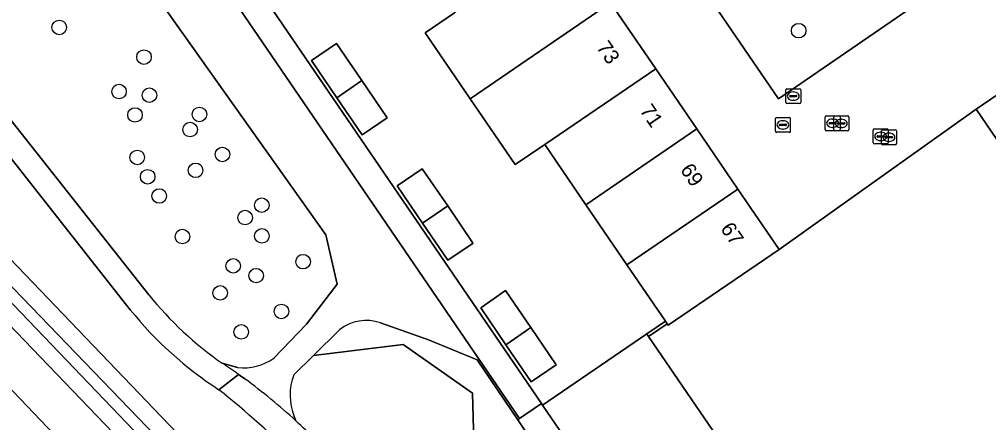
# Model space of a CAD drawing. Extents: x 155275 to 156265, y 382654 to 383635.
# Drawn here: x 155429.6 to 155494.7, y 382926 to 382953 of the extents above; entities that cross this region are included whole.
import ezdxf

# ---------------------------------------------------------------- set-up
doc = ezdxf.new("R2010")
doc.units = 0
for name, color, linetype in [('IMGEO_Boom', 7, 'Continuous'), ('IMGEO_Brandkraan', 7, 'Continuous'), ('IMGEO_Erf', 7, 'Continuous'), ('IMGEO_Fietspad_gesloten', 7, 'Continuous'), ('IMGEO_Groenvoorziening', 7, 'Continuous'), ('IMGEO_Muur', 7, 'Continuous'), ('IMGEO_Oever', 7, 'Continuous'), ('IMGEO_Pand', 7, 'Continuous'), ('IMGEO_Pand_nummerreeks', 7, 'Continuous'), ('IMGEO_Rioolput', 7, 'Continuous'), ('IMGEO_Voetpad_halfverhard', 7, 'Continuous'), ('IMGEO_Voetpad_open', 7, 'Continuous'), ('IMGEO_Waterloop', 7, 'Continuous')]:
    doc.layers.add(name, color=color, linetype=linetype)

msp = doc.modelspace()

# ---------------------------------------------------------------- linework, layer by layer
at = {"layer": 'IMGEO_Boom'}
for centre in [(155432.24, 382952.505), (155481.902, 382952.289), (155437.931, 382950.514), (155436.258, 382948.196), (155438.298, 382947.953), (155437.327, 382946.625), (155441.655, 382946.66), (155441.029, 382945.641), (155437.482, 382943.771), (155443.2, 382943.968), (155441.394, 382942.901), (155438.179, 382942.47), (155438.956, 382941.179), (155445.842, 382940.562), (155444.725, 382939.731), (155440.517, 382938.455), (155445.851, 382938.496), (155443.923, 382936.486), (155448.619, 382936.765), (155445.466, 382935.829), (155443.05, 382934.666), (155447.166, 382933.425), (155444.463, 382932.047)]:
    msp.add_circle(centre, 0.489, dxfattribs=at)
at = {"layer": 'IMGEO_Brandkraan'}
for p, q in [((155483.755, 382946.568), (155484.607, 382946.568)), ((155484.334, 382946.556), (155485.186, 382946.556)), ((155483.68, 382945.642), (155483.68, 382946.494)), ((155483.939, 382946.062), (155483.939, 382946.074)), ((155484.377, 382946.025), (155483.979, 382946.025)), ((155483.982, 382946.111), (155484.38, 382946.111)), ((155484.168, 382946.348), (155484.193, 382946.348)), ((155484.259, 382945.63), (155484.259, 382946.482)), ((155484.423, 382946.074), (155484.423, 382946.062)), ((155484.518, 382946.05), (155484.518, 382946.062)), ((155484.956, 382946.013), (155484.558, 382946.013)), ((155484.561, 382946.099), (155484.959, 382946.099)), ((155484.681, 382946.494), (155484.681, 382945.642)), ((155484.747, 382946.336), (155484.772, 382946.336)), ((155485.002, 382946.062), (155485.002, 382946.05)), ((155485.26, 382946.482), (155485.26, 382945.63)), ((155484.607, 382945.568), (155483.755, 382945.568)), ((155484.191, 382945.788), (155484.166, 382945.788)), ((155485.186, 382945.556), (155484.334, 382945.556)), ((155484.77, 382945.776), (155484.745, 382945.776)), ((155486.91, 382944.757), (155486.91, 382945.609)), ((155486.985, 382945.683), (155487.837, 382945.683)), ((155487.212, 382945.226), (155487.61, 382945.226)), ((155487.398, 382945.463), (155487.423, 382945.463)), ((155487.462, 382944.697), (155487.462, 382945.549)), ((155487.537, 382945.623), (155488.389, 382945.623)), ((155487.911, 382945.609), (155487.911, 382944.757)), ((155487.95, 382945.403), (155487.975, 382945.403)), ((155488.463, 382945.549), (155488.463, 382944.697)), ((155487.837, 382944.683), (155486.985, 382944.683)), ((155487.169, 382945.177), (155487.169, 382945.189)), ((155487.607, 382945.14), (155487.209, 382945.14)), ((155487.421, 382944.903), (155487.396, 382944.903)), ((155488.389, 382944.623), (155487.537, 382944.623)), ((155487.653, 382945.189), (155487.653, 382945.177)), ((155487.721, 382945.117), (155487.721, 382945.129)), ((155488.159, 382945.08), (155487.761, 382945.08)), ((155487.764, 382945.166), (155488.162, 382945.166)), ((155487.973, 382944.843), (155487.948, 382944.843)), ((155488.205, 382945.129), (155488.205, 382945.117))]:
    msp.add_line(p, q, dxfattribs=at)
for points in [[(155483.755, 382946.568), (155484.607, 382946.568)], [(155484.334, 382946.556), (155485.186, 382946.556)], [(155483.68, 382945.642), (155483.68, 382946.494)], [(155484.259, 382945.63), (155484.259, 382946.482)], [(155484.681, 382946.494), (155484.681, 382945.642)], [(155485.26, 382946.482), (155485.26, 382945.63)], [(155484.607, 382945.568), (155483.755, 382945.568)], [(155485.186, 382945.556), (155484.334, 382945.556)], [(155486.91, 382944.757), (155486.91, 382945.609)], [(155486.985, 382945.683), (155487.837, 382945.683)], [(155487.462, 382944.697), (155487.462, 382945.549)], [(155487.537, 382945.623), (155488.389, 382945.623)], [(155487.911, 382945.609), (155487.911, 382944.757)], [(155488.463, 382945.549), (155488.463, 382944.697)], [(155487.837, 382944.683), (155486.985, 382944.683)], [(155488.389, 382944.623), (155487.537, 382944.623)]]:
    msp.add_lwpolyline(points, dxfattribs=at)
for centre, radius, start, end in [((155483.757, 382946.492), 0.0765, 91.55205, 178.44795), ((155483.757, 382946.492), 0.0765, 91.55205, 178.44795), ((155484.336, 382946.48), 0.0765, 91.55205, 178.44795), ((155484.336, 382946.48), 0.0765, 91.55205, 178.44795), ((155484.605, 382946.492), 0.0765, 1.55205, 88.44795), ((155484.605, 382946.492), 0.0765, 1.55205, 88.44795), ((155485.184, 382946.48), 0.0765, 1.55205, 88.44795), ((155485.184, 382946.48), 0.0765, 1.55205, 88.44795), ((155483.979, 382946.071), 0.0403, 85.87752, 175.75265), ((155483.976, 382946.061), 0.0366, 178.93798, 274.71019), ((155484.38, 382946.068), 0.043, 264.86636, 352.45326), ((155484.384, 382946.073), 0.0386, 1.73085, 96.63898), ((155484.558, 382946.059), 0.0403, 85.87752, 175.75265), ((155484.555, 382946.049), 0.0366, 178.93798, 274.71019), ((155484.959, 382946.056), 0.043, 264.86636, 352.45326), ((155484.963, 382946.061), 0.0386, 1.73085, 96.63898), ((155483.757, 382945.644), 0.0765, 181.55205, 268.44795), ((155483.757, 382945.644), 0.0765, 181.55205, 268.44795), ((155484.336, 382945.632), 0.0765, 181.55205, 268.44795), ((155484.336, 382945.632), 0.0765, 181.55205, 268.44795), ((155484.605, 382945.644), 0.0765, 271.55205, 358.44795), ((155484.605, 382945.644), 0.0765, 271.55205, 358.44795), ((155485.184, 382945.632), 0.0765, 271.55205, 358.44795), ((155485.184, 382945.632), 0.0765, 271.55205, 358.44795), ((155486.987, 382945.607), 0.0765, 91.55205, 178.44795), ((155486.987, 382945.607), 0.0765, 91.55205, 178.44795), ((155487.209, 382945.186), 0.0403, 85.87752, 175.75265), ((155487.539, 382945.547), 0.0765, 91.55205, 178.44795), ((155487.539, 382945.547), 0.0765, 91.55205, 178.44795), ((155487.614, 382945.188), 0.0386, 1.73085, 96.63898), ((155487.835, 382945.607), 0.0765, 1.55205, 88.44795), ((155487.835, 382945.607), 0.0765, 1.55205, 88.44795), ((155488.387, 382945.547), 0.0765, 1.55205, 88.44795), ((155488.387, 382945.547), 0.0765, 1.55205, 88.44795), ((155486.987, 382944.759), 0.0765, 181.55205, 268.44795), ((155486.987, 382944.759), 0.0765, 181.55205, 268.44795), ((155487.206, 382945.176), 0.0366, 178.93798, 274.71019), ((155487.539, 382944.699), 0.0765, 181.55205, 268.44795), ((155487.539, 382944.699), 0.0765, 181.55205, 268.44795), ((155487.61, 382945.183), 0.043, 264.86636, 352.45326), ((155487.761, 382945.126), 0.0403, 85.87752, 175.75265), ((155487.758, 382945.116), 0.0366, 178.93798, 274.71019), ((155487.835, 382944.759), 0.0765, 271.55205, 358.44795), ((155487.835, 382944.759), 0.0765, 271.55205, 358.44795), ((155488.162, 382945.123), 0.043, 264.86636, 352.45326), ((155488.166, 382945.128), 0.0386, 1.73085, 96.63898), ((155488.387, 382944.699), 0.0765, 271.55205, 358.44795), ((155488.387, 382944.699), 0.0765, 271.55205, 358.44795)]:
    msp.add_arc(centre, radius, start, end, dxfattribs=at)
for centre, major_axis, ratio, start_param, end_param in [((155484.167, 382946.068), (-0.387, 0.002), 0.722429, 4.712389, 7.853982), ((155484.192, 382946.068), (-0.39, 0.002), 0.717154, 1.570796, 4.712389), ((155484.746, 382946.056), (-0.387, 0.002), 0.722429, 4.712389, 7.853982), ((155484.771, 382946.056), (-0.39, 0.002), 0.717154, 1.570796, 4.712389), ((155487.397, 382945.183), (-0.387, 0.002), 0.722429, 4.712389, 7.853982), ((155487.422, 382945.183), (-0.39, 0.002), 0.717154, 1.570796, 4.712389), ((155487.949, 382945.123), (-0.387, 0.002), 0.722429, 4.712389, 7.853982), ((155487.974, 382945.123), (-0.39, 0.002), 0.717154, 1.570796, 4.712389)]:
    msp.add_ellipse(centre, major_axis=major_axis, ratio=ratio, start_param=start_param, end_param=end_param, dxfattribs=at)
at = {"layer": 'IMGEO_Erf'}
msp.add_lwpolyline([(155421.418, 382990.501), (155464.622, 382927.23), (155464.698, 382927.119), (155471.711, 382931.915), (155472.956, 382932.767), (155470.369, 382936.552), (155467.607, 382940.594), (155464.844, 382944.637), (155462.868, 382943.287), (155459.842, 382947.715), (155456.816, 382952.143), (155458.792, 382953.493)], dxfattribs=at)
for points in [[(155450.863, 382951.428), (155452.568, 382948.935), (155454.272, 382946.442), (155452.588, 382945.29), (155450.883, 382947.783), (155449.179, 382950.276)], [(155493.818, 382947.008), (155480.587, 382937.595), (155473.132, 382932.509), (155473.073, 382932.596), (155471.827, 382931.745), (155493.084, 382900.658), (155497.755, 382906.335), (155491.194, 382911.739), (155505.778, 382929.47), (155504.79, 382930.919)], [(155456.623, 382943.004), (155458.329, 382940.509), (155460.006, 382938.056), (155460.035, 382938.014), (155458.35, 382936.862), (155456.645, 382939.357), (155454.939, 382941.853)], [(155462.212, 382934.83), (155463.919, 382932.334), (155465.625, 382929.838), (155463.941, 382928.687), (155462.24, 382931.186), (155460.549, 382933.67)], [(155464.698, 382927.119), (155464.622, 382927.23), (155463.155, 382926.228), (155463.032, 382926.144), (155485.973, 382892.026), (155486.483, 382892.646), (155487.457, 382893.827)]]:
    msp.add_lwpolyline(points, close=True, dxfattribs=at)
at = {"layer": 'IMGEO_Fietspad_gesloten'}
msp.add_lwpolyline([(155467.471, 382885.215), (155466.274, 382886.546), (155462.125, 382891.56), (155457.382, 382897.564), (155452.381, 382903.663), (155418.229, 382939.486), (155388.973, 382969.911), (155384.202, 382974.94), (155380.679, 382978.82)], dxfattribs=at)
at = {"layer": 'IMGEO_Groenvoorziening'}
for points in [[(155416.626, 382994.342), (155408.98, 383005.536), (155405.665, 383004.391), (155426.03, 382972.515), (155450.141, 382938.572), (155450.906, 382935.259), (155448.856, 382932.565), (155446.663, 382930.282)], [(155446.663, 382930.282), (155448.856, 382932.565), (155450.906, 382935.259), (155450.141, 382938.572), (155426.03, 382972.515), (155405.665, 383004.391)], [(155453.817, 382932.648), (155457.031, 382931.517), (155460.318, 382930.181), (155463.032, 382926.144), (155463.155, 382926.228), (155416.626, 382994.342)], [(155380.679, 382978.82), (155384.202, 382974.94), (155388.973, 382969.911), (155418.229, 382939.486), (155452.381, 382903.663), (155457.382, 382897.564), (155462.125, 382891.56), (155466.274, 382886.546), (155466.522, 382886.637), (155468.811, 382887.342)], [(155393.288, 382974.213), (155447.775, 382917.285)], [(155447.775, 382917.285), (155454.703, 382909.926), (155460.293, 382903.543), (155463.956, 382899.45), (155466.518, 382897.024), (155467.762, 382895.538), (155468.224, 382894.705), (155468.233, 382894.159), (155467.888, 382893.76), (155466.948, 382893.209), (155466.064, 382892.869), (155465.377, 382892.557), (155464.556, 382892.407), (155463.66, 382893.099), (155462.999, 382893.797), (155462.379, 382895.436), (155460.89, 382898.156), (155455.27, 382904.593), (155445.485, 382915.19), (155436.945, 382924.144), (155416.355, 382945.549), (155391.148, 382972.039)], [(155428.35, 382947.092), (155438.264, 382934.539)], [(155437.014, 382933.541), (155427.167, 382946.015)], [(155447.986, 382929.172), (155449.307, 382930.467), (155451.068, 382932.194)], [(155451.068, 382932.194), (155449.307, 382930.467), (155455.341, 382931.206), (155459.985, 382927.921), (155460.189, 382920.613), (155462.731, 382920.535), (155484.389, 382890.104), (155485.973, 382892.026), (155463.032, 382926.144)], [(155463.032, 382926.144), (155460.318, 382930.181), (155457.031, 382931.517), (155453.817, 382932.648)], [(155483.002, 382888.419), (155484.389, 382890.104), (155462.731, 382920.535), (155460.189, 382920.613), (155459.985, 382927.921), (155455.341, 382931.206), (155449.307, 382930.467)], [(155449.307, 382930.467), (155447.986, 382929.172)], [(155443.193, 382929.938), (155444.216, 382929.65)], [(155444.216, 382929.65), (155443.193, 382929.938)], [(155444.284, 382929.195), (155444.705, 382928.891)], [(155448.128, 382926.079), (155448.028, 382926.358)], [(155448.028, 382926.358), (155448.128, 382926.079)]]:
    msp.add_lwpolyline(points, dxfattribs=at)
msp.add_lwpolyline([(155486.475, 382964.787), (155482.709, 382967.951), (155470.174, 382971.495), (155467.088, 382967.393), (155480.543, 382947.7), (155491.103, 382954.98), (155488.826, 382961.54)], close=True, dxfattribs=at)
for centre, radius, start, end in [((155456.379, 382949.005), 23.183, 218.60931, 235.33311), ((155456.374, 382948.994), 24.771, 218.59752, 237.24125), ((155452.849, 382929.958), 2.859, 70.21158, 128.54403), ((155452.849, 382929.958), 2.859, 70.21158, 128.54403), ((155444.585, 382933.274), 3.643, 264.18504, 304.77821), ((155444.585, 382933.274), 3.643, 264.18504, 304.77821), ((155424.926, 382901.943), 33.427, 54.61277, 56.87542), ((155451.602, 382927.819), 3.861, 159.48201, 202.22819), ((155451.602, 382927.819), 3.861, 159.48201, 202.22819), ((155420.948, 382896.483), 40.183, 47.43702, 53.75666), ((155404.991, 382880.696), 60.79, 37.98723, 51.33615), ((155420.193, 382895.654), 41.304, 44.88947, 47.44342)]:
    msp.add_arc(centre, radius, start, end, dxfattribs=at)
at = {"layer": 'IMGEO_Muur'}
msp.add_lwpolyline([(155473.073, 382932.596), (155472.956, 382932.767), (155471.711, 382931.915), (155471.827, 382931.745)], close=True, dxfattribs=at)
at = {"layer": 'IMGEO_Oever'}
for points in [[(155391.148, 382972.039), (155416.355, 382945.549), (155436.945, 382924.144), (155445.485, 382915.19), (155455.27, 382904.593), (155460.89, 382898.156), (155462.379, 382895.436), (155462.999, 382893.797), (155463.66, 382893.099), (155464.556, 382892.407), (155465.377, 382892.557), (155466.064, 382892.869), (155466.948, 382893.209), (155467.888, 382893.76), (155468.233, 382894.159), (155468.224, 382894.705), (155467.762, 382895.538), (155466.518, 382897.024), (155463.956, 382899.45), (155460.293, 382903.543), (155454.703, 382909.926), (155447.775, 382917.285), (155393.288, 382974.213)], [(155394.163, 382971.559), (155413.378, 382951.535), (155426.165, 382938.046), (155446.47, 382917.004)], [(155446.47, 382917.004), (155455.076, 382907.87), (155458.688, 382903.767), (155461.85, 382899.868), (155465.852, 382894.549), (155466.325, 382893.762), (155465.272, 382893.187), (155464.84, 382894.03), (155461.288, 382899.411), (155458.196, 382903.31), (155445.925, 382916.371), (155412.904, 382950.833), (155393.654, 382970.786)]]:
    msp.add_lwpolyline(points, dxfattribs=at)
at = {"layer": 'IMGEO_Pand'}
for points in [[(155466.247, 382958.586), (155458.792, 382953.493), (155456.816, 382952.143), (155459.842, 382947.715), (155469.272, 382954.159)], [(155472.298, 382949.729), (155469.272, 382954.159), (155459.842, 382947.715), (155462.868, 382943.287), (155464.844, 382944.637)], [(155500.853, 382951.806), (155493.818, 382947.008), (155504.79, 382930.919), (155511.816, 382935.729)], [(155450.863, 382951.428), (155449.179, 382950.276), (155450.883, 382947.783), (155452.568, 382948.935)], [(155475.059, 382945.687), (155472.298, 382949.729), (155464.844, 382944.637), (155467.607, 382940.594)], [(155452.568, 382948.935), (155450.883, 382947.783), (155452.588, 382945.29), (155454.272, 382946.442)], [(155477.821, 382941.644), (155475.059, 382945.687), (155467.607, 382940.594), (155470.369, 382936.552)], [(155456.623, 382943.004), (155454.939, 382941.853), (155456.645, 382939.357), (155458.329, 382940.509)], [(155480.587, 382937.595), (155477.821, 382941.644), (155470.369, 382936.552), (155472.956, 382932.767), (155473.073, 382932.596), (155473.132, 382932.509)], [(155458.329, 382940.509), (155456.645, 382939.357), (155458.35, 382936.862), (155460.035, 382938.014), (155460.006, 382938.056)], [(155462.212, 382934.83), (155460.549, 382933.67), (155462.24, 382931.186), (155463.919, 382932.334)], [(155463.919, 382932.334), (155462.24, 382931.186), (155463.941, 382928.687), (155465.625, 382929.838)], [(155471.827, 382931.745), (155471.711, 382931.915), (155464.698, 382927.119), (155487.457, 382893.827), (155493.084, 382900.658)]]:
    msp.add_lwpolyline(points, close=True, dxfattribs=at)
at = {"layer": 'IMGEO_Rioolput'}
for p, q in [((155481.035, 382947.463), (155481.035, 382948.315)), ((155481.11, 382948.389), (155481.962, 382948.389)), ((155481.294, 382947.883), (155481.294, 382947.895)), ((155481.732, 382947.846), (155481.334, 382947.846)), ((155481.337, 382947.932), (155481.735, 382947.932)), ((155481.523, 382948.169), (155481.548, 382948.169)), ((155481.778, 382947.895), (155481.778, 382947.883)), ((155482.036, 382948.315), (155482.036, 382947.463)), ((155481.962, 382947.389), (155481.11, 382947.389)), ((155481.546, 382947.609), (155481.521, 382947.609)), ((155480.34, 382945.531), (155480.34, 382946.383)), ((155480.415, 382946.457), (155481.267, 382946.457)), ((155480.599, 382945.951), (155480.599, 382945.963)), ((155481.037, 382945.914), (155480.639, 382945.914)), ((155480.642, 382946), (155481.04, 382946)), ((155480.828, 382946.237), (155480.853, 382946.237)), ((155481.083, 382945.963), (155481.083, 382945.951)), ((155481.341, 382946.383), (155481.341, 382945.531)), ((155481.267, 382945.457), (155480.415, 382945.457)), ((155480.851, 382945.677), (155480.826, 382945.677))]:
    msp.add_line(p, q, dxfattribs=at)
for points in [[(155481.035, 382947.463), (155481.035, 382948.315)], [(155481.11, 382948.389), (155481.962, 382948.389)], [(155482.036, 382948.315), (155482.036, 382947.463)], [(155481.962, 382947.389), (155481.11, 382947.389)], [(155480.34, 382945.531), (155480.34, 382946.383)], [(155480.415, 382946.457), (155481.267, 382946.457)], [(155481.341, 382946.383), (155481.341, 382945.531)], [(155481.267, 382945.457), (155480.415, 382945.457)]]:
    msp.add_lwpolyline(points, dxfattribs=at)
for centre, radius, start, end in [((155481.112, 382948.313), 0.0765, 91.55205, 178.44795), ((155481.112, 382948.313), 0.0765, 91.55205, 178.44795), ((155481.334, 382947.892), 0.0403, 85.87752, 175.75265), ((155481.331, 382947.882), 0.0366, 178.93798, 274.71019), ((155481.735, 382947.889), 0.043, 264.86636, 352.45326), ((155481.739, 382947.894), 0.0386, 1.73085, 96.63898), ((155481.96, 382948.313), 0.0765, 1.55205, 88.44795), ((155481.96, 382948.313), 0.0765, 1.55205, 88.44795), ((155481.112, 382947.465), 0.0765, 181.55205, 268.44795), ((155481.112, 382947.465), 0.0765, 181.55205, 268.44795), ((155481.96, 382947.465), 0.0765, 271.55205, 358.44795), ((155481.96, 382947.465), 0.0765, 271.55205, 358.44795), ((155480.417, 382946.381), 0.0765, 91.55205, 178.44795), ((155480.417, 382946.381), 0.0765, 91.55205, 178.44795), ((155480.639, 382945.96), 0.0403, 85.87752, 175.75265), ((155480.636, 382945.95), 0.0366, 178.93798, 274.71019), ((155481.04, 382945.957), 0.043, 264.86636, 352.45326), ((155481.044, 382945.962), 0.0386, 1.73085, 96.63898), ((155481.265, 382946.381), 0.0765, 1.55205, 88.44795), ((155481.265, 382946.381), 0.0765, 1.55205, 88.44795), ((155480.417, 382945.533), 0.0765, 181.55205, 268.44795), ((155480.417, 382945.533), 0.0765, 181.55205, 268.44795), ((155481.265, 382945.533), 0.0765, 271.55205, 358.44795), ((155481.265, 382945.533), 0.0765, 271.55205, 358.44795)]:
    msp.add_arc(centre, radius, start, end, dxfattribs=at)
for centre, major_axis, ratio, start_param, end_param in [((155481.522, 382947.889), (-0.387, 0.002), 0.722429, 4.712389, 7.853982), ((155481.547, 382947.889), (-0.39, 0.002), 0.717154, 1.570796, 4.712389), ((155480.827, 382945.957), (-0.387, 0.002), 0.722429, 4.712389, 7.853982), ((155480.852, 382945.957), (-0.39, 0.002), 0.717154, 1.570796, 4.712389)]:
    msp.add_ellipse(centre, major_axis=major_axis, ratio=ratio, start_param=start_param, end_param=end_param, dxfattribs=at)
at = {"layer": 'IMGEO_Voetpad_halfverhard'}
for points in [[(155438.264, 382934.539), (155428.35, 382947.092)], [(155427.167, 382946.015), (155437.014, 382933.541)], [(155442.97, 382928.163), (155444.284, 382929.195)], [(155444.705, 382928.891), (155444.284, 382929.195), (155442.97, 382928.163)]]:
    msp.add_lwpolyline(points, dxfattribs=at)
for centre, radius, start, end in [((155456.379, 382949.005), 23.183, 218.60931, 235.33311), ((155456.374, 382948.994), 24.771, 218.59752, 237.24125), ((155424.926, 382901.943), 33.427, 54.61277, 56.87542), ((155420.948, 382896.483), 40.183, 47.43702, 53.75666), ((155404.991, 382880.696), 60.79, 37.98723, 51.33615), ((155420.193, 382895.654), 41.304, 44.88947, 47.44342)]:
    msp.add_arc(centre, radius, start, end, dxfattribs=at)
at = {"layer": 'IMGEO_Voetpad_open'}
for points in [[(155499.817, 382960.988), (155492.631, 382956.034), (155491.103, 382954.98), (155480.543, 382947.7), (155467.088, 382967.393), (155466.292, 382968.557), (155449.288, 382993.444), (155447.393, 382996.217), (155448.793, 382997.09), (155471.008, 383010.94), (155474.212, 383012.937), (155475.461, 383013.715), (155494.475, 383025.569), (155496.669, 383026.937)], [(155436.437, 383002.224), (155438.739, 382998.854), (155441.846, 382994.306), (155444.917, 382989.81), (155447.989, 382985.314), (155451.464, 382980.227), (155454.366, 382975.978), (155457.268, 382971.73), (155460.693, 382966.717), (155463.669, 382962.361), (155466.247, 382958.586), (155469.272, 382954.159), (155472.298, 382949.729), (155475.059, 382945.687), (155477.821, 382941.644), (155480.587, 382937.595), (155493.818, 382947.008), (155500.853, 382951.806)], [(155416.626, 382994.342), (155463.155, 382926.228), (155464.622, 382927.23), (155421.418, 382990.501)]]:
    msp.add_lwpolyline(points, dxfattribs=at)
at = {"layer": 'IMGEO_Waterloop'}
msp.add_lwpolyline([(155393.654, 382970.786), (155412.904, 382950.833), (155445.925, 382916.371), (155458.196, 382903.31), (155461.288, 382899.411), (155464.84, 382894.03), (155465.272, 382893.187), (155466.325, 382893.762), (155465.852, 382894.549), (155461.85, 382899.868), (155458.688, 382903.767), (155455.076, 382907.87), (155446.47, 382917.004), (155426.165, 382938.046), (155413.378, 382951.535), (155394.163, 382971.559)], dxfattribs=at)

# ---------------------------------------------------------------- texts
at = {"layer": 'IMGEO_Pand_nummerreeks'}
for s, p in [('73', (155468.287, 382951.168)), ('71', (155471.19, 382946.919)), ('69', (155473.909, 382942.938)), ('67', (155476.612, 382938.982))]:
    msp.add_text(s, height=1, rotation=304.33715, dxfattribs=at).set_placement(p)

doc.saveas('drawing.dxf')
